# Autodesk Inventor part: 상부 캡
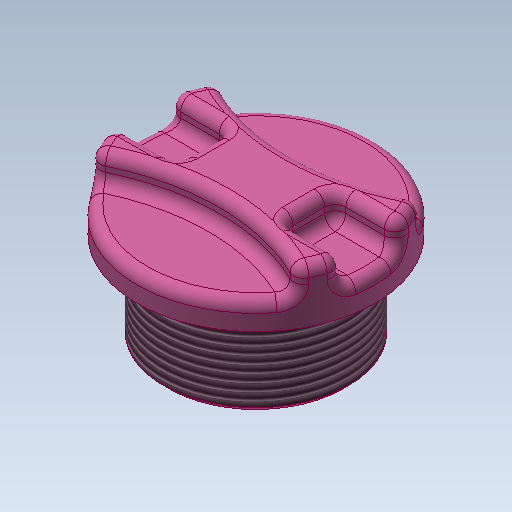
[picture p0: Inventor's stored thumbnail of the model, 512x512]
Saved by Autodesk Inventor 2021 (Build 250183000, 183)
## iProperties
Created: 2016-09
Part Number: 상부 캡
Material: ABS 플라스틱
Document SubType Name: Modeling
Designer: mduedu
Density: 1.06 g/cm^3
Appearance: 분홍색
Author: mduedu
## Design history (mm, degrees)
sketch "스케치1"
  geometry: C1 r 22.5 at (0, 0); 1 further point
  constraints: 1 centre point, 1 coincident
  dimensions: "d0" = 45 diameter of C1
extrude "돌출1" new body sketch "스케치1" distance "d1" = 10; taper "d2" = 0 deg
sketch "스케치2" dims "d4" = 80
  geometry: C1 r 22.5 at (0, 0) reference; 3 further points
  constraints: 3 vertical alignment, 2 other
  dimensions: "d3" = 7 distance of point (0, 7) point (0, 0)
extrude "돌출2" cut sketch "스케치2" distance "d5" = 5; taper "d6" = 0 deg
sketch "스케치3"
  geometry: L1 (-22.5, 0)-(0, 0); L2 (-21.937, 5)-(-10, 5); L3 (-10, 5)-(-10, -5); L4 (-10, -5)-(-21.937, -5); A1 r 22.5 centre (0, 0) between (-19.118, 11.864) and (-19.118, -11.864) reference; A2 r 22.5 centre (0, 0) between (-21.937, 5) and (-21.937, -5); 1 further point
  constraints: 8 end point, 5 point on circle, 2 horizontal, 1 centre point, 1 coincident, 1 parallel, 1 perpendicular, 1 symmetric about line
  dimensions: "d7" = 10 distance from line of L3 point (0, 0); "d8" = 10 distance of L2.end L3.end
extrude "돌출3" cut sketch "스케치3" distance "d9" = 5; taper "d10" = 0 deg
fillet "모깎기1" dims "d11" = 2
fillet "모깎기2" dims "d12" = 2
fillet "모깎기3" dims "d13" = 2
sketch "스케치4"
  geometry: C1 r 17.5 at (0, 0); 1 further point
  constraints: 1 centre point, 1 coincident
  dimensions: "d14" = 35 diameter of C1
extrude "돌출4" join sketch "스케치4" distance "d15" = 17; taper "d16" = 0 deg
sketch "스케치5"
  geometry: C1 r 12.5 at (0, 0); 1 further point
  constraints: 1 centre point, 1 coincident
  dimensions: "d17" = 25 diameter of C1
extrude "돌출5" cut sketch "스케치5" distance "d18" = 10; taper "d19" = 0 deg
fillet "모깎기4" dims "d20" = 3
feature "스레드1" dims "d21" = 10, "d22" = 0
chamfer "모따기1" distance "d23" = 1; stored, may be unused: second distance "d24" = 2, angle "d25" = 45 deg
node "솔리드1"
mirror "대칭1"
mirror "대칭2"
node "투영된 루프1"
